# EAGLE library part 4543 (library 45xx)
BCD to 7-segment LCD DECODER
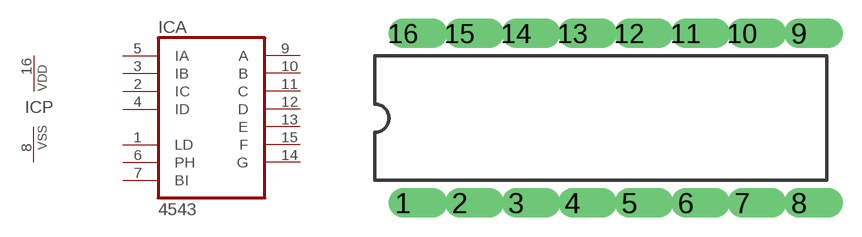
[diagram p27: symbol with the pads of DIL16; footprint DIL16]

Designator prefix IC; gates A=4543 P=PWRN

## 4543N  [DIL16]
1  A:LD  in
2  A:IC  in
3  A:IB  in
4  A:ID  in
5  A:IA  in
6  A:PH  in
7  A:BI  in
8  P:VSS  pwr
9  A:A  out
10  A:B  out
11  A:C  out
12  A:D  out
13  A:E  out
14  A:G  out
15  A:F  out
16  P:VDD  pwr

## Footprint DIL16 (pad centres in mm)
Dual In Line
drill 0.813 offset: 1 -8.89,-3.81; 2 -6.35,-3.81; 3 -3.81,-3.81; 4 -1.27,-3.81; 5 1.27,-3.81; 6 3.81,-3.81; 7 6.35,-3.81; 8 8.89,-3.81; 9 8.89,3.81; 10 6.35,3.81; 11 3.81,3.81; 12 1.27,3.81; 13 -1.27,3.81; 14 -3.81,3.81; 15 -6.35,3.81; 16 -8.89,3.81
